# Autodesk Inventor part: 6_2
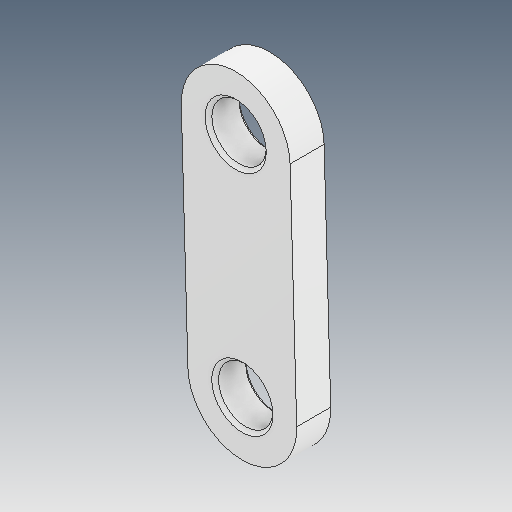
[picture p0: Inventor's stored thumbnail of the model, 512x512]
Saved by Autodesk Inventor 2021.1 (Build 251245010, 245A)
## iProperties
Created: 2021-06
Part Number: 6_2
Material: Ogólny
Document SubType Name: Modeling
Designer: user
Density: 1 g/cm^3
Appearance: Domyślna
Author: user
Revision Number: ÈÎºÎ
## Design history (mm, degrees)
feature "ÊäÈë1"
node "Bryła1"
